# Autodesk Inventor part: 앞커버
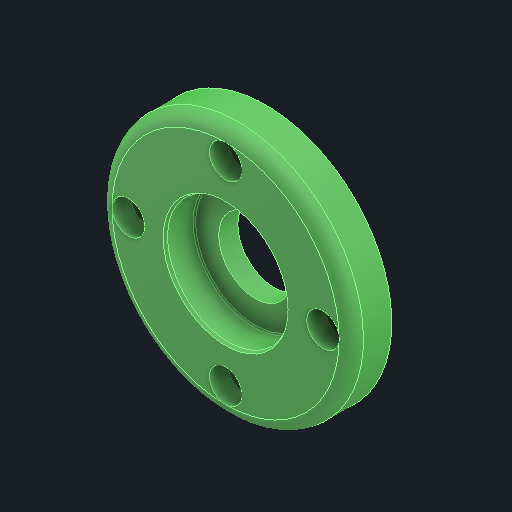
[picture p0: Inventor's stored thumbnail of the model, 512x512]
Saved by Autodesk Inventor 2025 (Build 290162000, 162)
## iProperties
Created: 2025-08
Part Number: 앞커버
Material: 알루미늄 6061
Document SubType Name: Modeling
Designer: infra023
Density: 2.71 g/cm^3
Appearance: 기본값
Author: jhkim
Sending System: Autodesk Inventor 2026
Preprocessor: ST-DEVELOPER v20.1
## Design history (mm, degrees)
feature "솔리드1"
node "솔리드2"
